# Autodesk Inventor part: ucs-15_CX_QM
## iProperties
Shininess: 20.0
Length Units: 11269
Angle Units: 11279
Time Units: 11290
Mass Units: 11283
Length Display Precision: 2
Angle Display Precision: 2
Part Number: ucs-15_CX_QM
Material: nicht zugewiesen
Document SubType Name: Modellieren
Description: ucs-15/CX/QM
Checked By: Alves
Created: 2005-08
Designer: Ohle
Manufacturer: Standard
Standards Organization: Custom
Density: 0.0
Volumn: 0.0
Area: 0.0
PropertySet Name: Model Information
Control State: 0
Master: False
Checked Out: False
Last Check In By: ohle
Last Check In Date: 2005-08-23
BESTELLNUMMER: ucs-15/CX/QM
ME: ST
Title: ucs Sensoren
Author: Ohle
Comments: keine Bemerkung
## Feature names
1. Grundkörper [Extrusion]
2. Prismenschiene,unten [Extrusion]
3. Rundung 0,3_unten [Fillet]
4. Tastenfeld LED [Extrusion]
5. LED [Extrusion]
6. Taste [Extrusion]
7. Rundung GK1 [Fillet]
8. Rundung GK2 [Fillet]
9. Fase Taste1 [Chamfer]
10. Fase Taste2 [Chamfer]
11. Gewindeansatz [Revolution]
12. Kabelausgang [Extrusion]
13. Rundung KA1 [Fillet]
14. Rundung KA2 [Fillet]
15. Pole [Extrusion]
16. Rundung Pole [Fillet]
17. Verdrehsicherung [Extrusion]
18. Gewinde M4 [Hole]
19. Prismenschiene,seitlich [Extrusion]
20. Rundung 0,3_seitlich [Fillet]
21. Kerbe Gewindeansatz [Extrusion]
22. Drehung2 [Revolution]
23. Extrusion13
24. Extrusion14
25. Rundung8 [Fillet]
26. Rundung9 [Fillet]
27. Rundung10 [Fillet]
28. Extrusion15
29. Extrusion16
